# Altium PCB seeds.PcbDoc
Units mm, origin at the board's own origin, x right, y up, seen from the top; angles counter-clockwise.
Board outline 80 x 51 mm, 2 copper layers (Top Layer, Bottom Layer); 51 components, 49 nets, 224 pads, 44 vias.
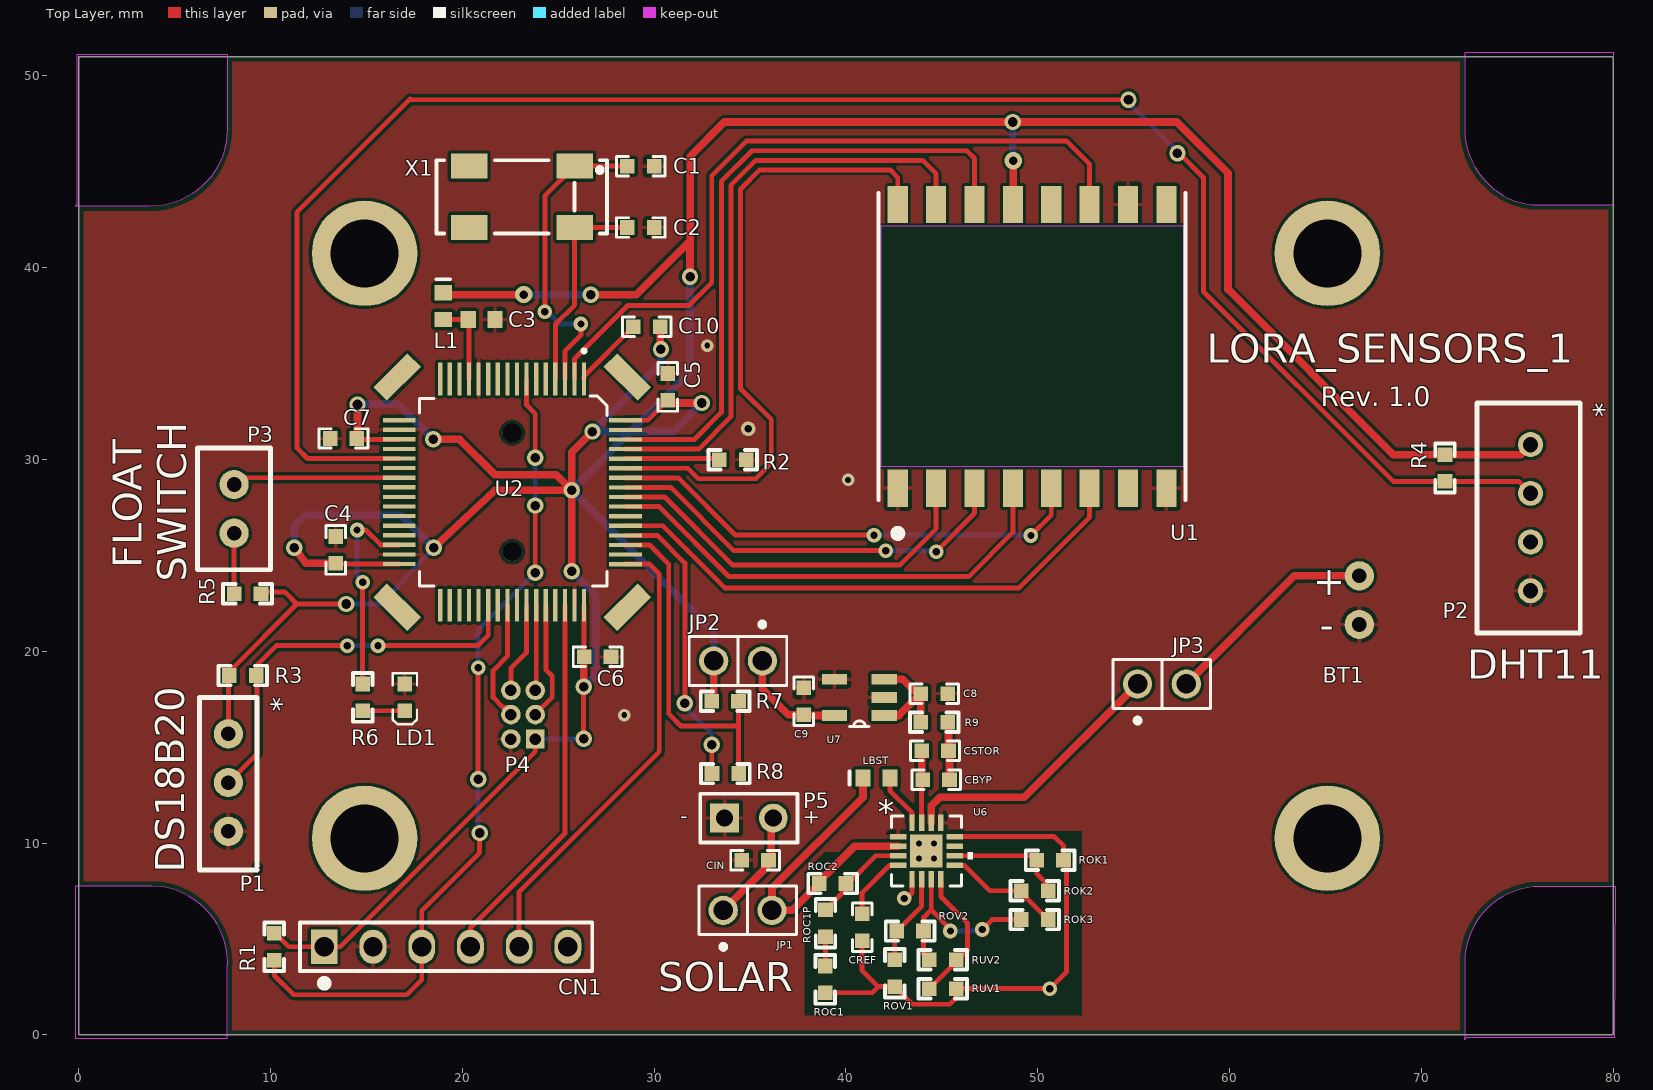
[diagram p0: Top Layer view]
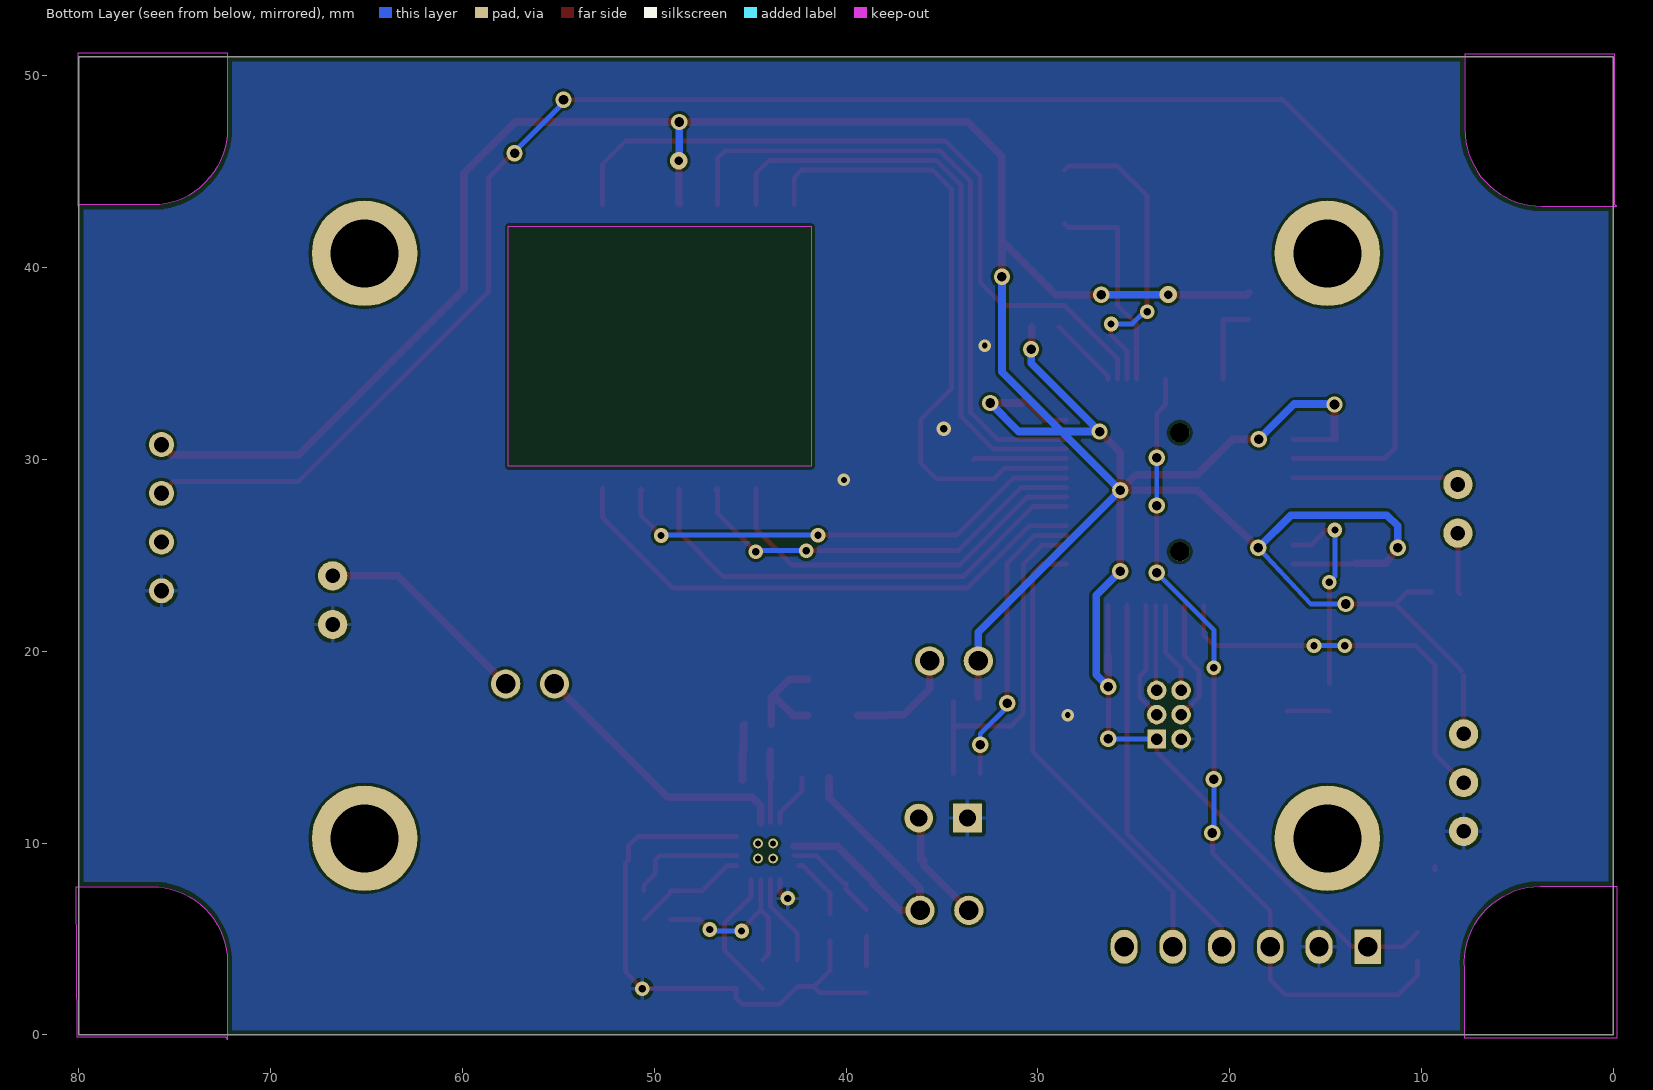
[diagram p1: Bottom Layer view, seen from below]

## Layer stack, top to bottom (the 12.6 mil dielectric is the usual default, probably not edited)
Top Solder: solder mask 0.0102, Solder Resist, Dk 3.5
Top Layer: signal copper 0.0356
Dielectric 1: dielectric 0.32, FR-4, Dk 4.8
Bottom Layer: signal copper 0.0356
Bottom Solder: solder mask 0.0102, Solder Resist, Dk 3.5

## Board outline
0,0 80,0 80,51 0,51
cut-out: 7.74,51.12 7.74,47.22 cw(c3.73,47.22) 3.73,43.21 -0.19,43.21 ccw(c-0.19,43.31) -0.09,43.31 -0.09,51.12
cut-out: 80.12,7.74 76.21,7.74 ccw(c76.21,3.78) 72.25,3.78 72.25,-0.24 cw(c72.38,-0.24) 72.38,-0.11 80.07,-0.11
cut-out: -0.18,-0.16 7.75,-0.16 7.75,3.46 ccw(c3.747,3.747) 3.46,7.75 -0.18,7.75
cut-out: 72.25,51.2 72.25,47.22 ccw(c76.162,47.22) 73.396,44.454 73.477,44.373 ccw(c76.115,47.011) 76.115,43.28 79.952,43.28 cw(c79.952,43.212) 80.02,43.212 80.02,51.2

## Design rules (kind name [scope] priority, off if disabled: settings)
BoardOutlineClearance [All] p1: gap=0.25 ignorepadtopadclearanceinfootprint=FALSE except(0: Arc-SplitContinuation Track-SplitContinuation SMDPad-SplitContinuation THPad-SplitContinuation Via-SplitContinuation Fill-SplitContinuation Poly-SplitContinuation Region-SplitContinuation Text-SplitContinuation)
Clearance Clearance-xPP-xTP-xTT [All] p1: gap=0.15 ignorepadtopadclearanceinfootprint=FALSE except(0: Arc-Hole Track-Hole SMDPad-Hole THPad-Hole Via-Hole Fill-Hole Poly-Hole Region-Hole Text-Hole)
ComponentClearance [All] p1: gap=0.25 collisioncheckmode=3 verticalgap=0.25 showdistances=FALSE
DiffPairsRouting [All] p1: maxlimit=0.25 minlimit=0.25 mostfreqgap=0.25 toplayer_minwidth=0.381 toplayer_maxwidth=0.381 toplayer_prefwidth=0.381 bottomlayer_minwidth=0.381 bottomlayer_maxwidth=0.381 bottomlayer_prefwidth=0.381 maxuncoupledlength=12.5
Height [All] p1: minheight=0 maxheight=25 prefheight=12.5
HoleSize HoleSize-PTH [All] p1: absolutevalues=TRUE maxlimit=3.6 minlimit=0.3 maxpercent=80.000 minpercent=20.000
HoleToHoleClearance [All] p1: gap=0.35 allowstackedmicrovias=TRUE
MinimumAnnularRing "Minimum IAR  >0.45mm" [((ObjectKind = 'Pad') OR (ObjectKind = 'Via')) And (Layer = 'MultiLayer') And (HoleDiameter > AsMM(0.45))] p1: minimumring=0.114 // minimum inner annular ring for pads > 0.45mm finished hole size
MinimumAnnularRing "Minimum IAR <=0.45mm" [((ObjectKind = 'Pad') OR (ObjectKind = 'Via')) And (Layer = 'MultiLayer') And (HoleDiameter <= AsMM(0.45))] p2: minimumring=0.175 // minimum inner annular ring for pads <= 0.45mm finished hole size
MinimumSolderMaskSliver [All] p1: minsoldermaskwidth=0.025
PlaneClearance PlaneClearance-IPI [All] p1: clearance=0.25
PlaneConnect [All] p1: planeconnectstyle=Relief reliefexpansion=0.175 reliefentries=4 reliefconductorwidth=0.2 reliefairgap=0.2
PolygonConnect PolygonConnect-xTW [All] p1: connectstyle=Relief reliefconductorwidth=0.2 reliefentries=4 polygonreliefangle="90 Angle" airgapwidth=0.2
RoutingCorners [All] p1: cornerstyle=45-Degree minsetback=2.5 maxsetback=2.5
RoutingVias "RoutingVias > 0.45mm" [(ObjectKind = 'Via') And (HoleDiameter > AsMM(0.45))] p1: holewidth=0.5 width=0.85 viastyle="Through Hole" minholewidth=0.5 minwidth=0.85 maxholewidth=0.9 maxwidth=1.25 // finishet hole size > 0.45mm
RoutingVias "RoutingVias <= 0.45mm" [(ObjectKind = 'Via') And (HoleDiameter <= AsMM(0.45))] p2: holewidth=0.3 width=0.65 viastyle="Through Hole" minholewidth=0.25 minwidth=0.6 maxholewidth=0.45 maxwidth=0.8 // finishet hole size <= 0.45mm
ShortCircuit ShortCircuit_1 [not InAnyNet vs not InAnyNet] p1: allowed=TRUE
ShortCircuit [All] p2: allowed=FALSE
SilkToSilkClearance [All] p1: silktosilkclearance=0
SilkToSolderMaskClearance SilkscreenOverComponentPads [IsPad] p1: minsilkscreentomaskgap=0.025 clearancetoexposedcopper=TRUE
SolderMaskExpansion [All] p1: expansion=0
UnRoutedNet [All] p1: checkbadconnections=TRUE
Width Width-xTW [All] p1: maxlimit=1.5 minlimit=0.15 preferedwidth=0.2
17 further rules are at their usual default settings.

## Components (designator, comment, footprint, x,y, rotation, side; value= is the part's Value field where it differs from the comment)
BT1 "battery" BATTERY 66.76,23.94 r270 top
C1 "10pF[N/A]" 0603C 29.3,45.3 r180 top value=10pF
C2 "10pF[N/A]" 0603C 29.3,42.1 r180 top value=10pF
C3 "Cap Semi" 1608[0603] 21,37.3 r0 top value=0.1µF
C4 "100nF" 0603C 13.39,25.29 r270 top value=0.1µF
C5 "100nF" 0603C 30.7,33.79 r270 top value=0.1µF
C6 "100nF" 0603C 27.05,19.71 r180 top value=0.1µF
C7 "100nF" 0603C 13.8,31.1 r0 top value=0.1uF
C8 "1uF" 0603C 44.6,17.8 r0 top value=1000pF
C9 "2.2uF" 0603C 37.8,17.4 r90 top value=2.2µF
C10 "100nF" 0603C 29.61,36.92 r0 top value=0.1µF
CBYP "C_BYP" 0603C 44.7,13.3 r180 top value=10pF
CIN "C_HVR" 0603C 35.26,9.11 r180 top value=4700pF
CN1 "Header 6X1" 1*6P 12.8,4.6 r0 top
CREF "C_REF" 0603C 40.844,5.619 r270 top value=10pF
CSTOR "C_STOR" 0603C 44.644,14.819 r180 top value=4.7µF
JP1 "JP2" SIP2/2.54 33.6,6.5 r0 top
JP2 "JP2" SIP2/2.54 35.64,19.5 r180 top
JP3 "JP2" SIP2/2.54 55.2,18.3 r0 top
L1 "Bead" INDC1608L 19,38 r270 top value="600 OHM"
LBST "Inductor" INDC1608L 41.59,13.4 r0 top value=22nH
LD1 "Green" 0603D 17,17.599 r270 top value=571nm
P1 "ds18b20" ds18b20 7.8,15.7 r270 top
P2 "dht11" dht11 75.69,30.78 r270 top
P3 "float_switch" float_switch 8.1,28.7 r270 top
P4 "header_3x2" header_3x2 22.53,15.43 r90 top
P5 "Header 2" HDR1X2 33.67,11.31 r0 top
R1 "4K7" 0603R 10.2,4.6 r270 top value="4.7 kOhms"
R2 "4K7" 0603R 34.1,30 r0 top value="4.7 kOhms"
R3 "4K7" 0603R 8.55,18.74 r0 top value="4.7 kOhms"
R4 "4K7" 0603R 71.23,29.56 r90 top value="4.7 kOhms"
R5 "4K7" 0603R 8.8,23 r0 top value="4.7 kOhms"
R6 "510" 0603R 14.8,17.6 r90 top value="510 Ohms"
R7 "1K" 0603R 33.7,17.4 r180 top value="1 kOhm"
R8 "1K" 0603R 33.71,13.63 r0 top value="1 kOhm"
R9 "" 0603R 44.6,16.3 r0 top value=0ohm
ROC1 "R_OC1" 0603R 38.92,2.9 r270 top value=5.76M
ROC1P "R_OC1Plus" 0603R 38.93,5.83 r270 top value=10M
ROC2 "R_OC2" 0603R 39.3,7.9 r0 top value=4.12M
ROK1 "R_OK1" 0603R 50.644,9.119 r180 top value=3.74Mohm
ROK2 "R_OK2" 0603R 49.844,7.519 r180 top value=5.23Mohm
ROK3 "R_OK3" 0603R 49.844,6.019 r180 top value="909 kOhms"
ROV1 "R_OV1" 0603R 42.544,3.219 r270 top value=4.53Mohm
ROV2 "R_OV2" 0603R 43.344,5.419 r180 top value=5.62Mohm
RUV1 "R_UV1" 0603R 45.044,2.419 r0 top value=4.99Mohm
RUV2 "R_UV2" 0603R 45.044,3.919 r0 top value=4.99Mohm
U1 "RFM95W-868S2" XCVR_RFM95W-868S2 49.7,35.9 r90 top
U2 "MCU_LQFP64" LQFP64 22.6,28.3 r180 top
U6 "BQ25504_RGT_16" RGT16_1P7X1P7 44.194,9.594 r0 top
U7 "TPS78330DDCR" SOT95P280X110-5N 40.7,17.6 r180 top
X1 "32.768K[N/A]" XTAL_4SM_8X3R8 23.1,43.7 r180 top

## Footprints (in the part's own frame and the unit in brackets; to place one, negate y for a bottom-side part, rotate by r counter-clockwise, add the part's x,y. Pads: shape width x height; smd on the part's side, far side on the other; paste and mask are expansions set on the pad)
1*6P [mil]
  rect 55x70 hole 40: 1(0,0)
  oval 55x70 hole 40: 2(400,0) 3(100,0) 4(300,0) 5(200,0) 6(500,0)
  silkscreen extent -50,-82 550,50
0603C [mil]
  rect 30x30 smd: 1(27.5,0) 2(-27.5,0)
  silkscreen extent -50,-20 50,20
0603D [mil]
  rect 30x30 smd: 1(27.5,0) 2(-27.5,0)
  silkscreen extent -50,-25 55,25
0603R [mil]
  rect 30x30 smd: 1(27.5,0) 2(-27.5,0)
  silkscreen extent -50,-20 50,20
1608[0603] [mm] "Chip Capacitor, Body 1.6x0.8mm, IPC High Density"
  rect 0.8x0.9 smd: 1(-0.7,0) 2(0.7,0)
  body extent -0.87,-0.48 0.87,0.48, height 1.3
BATTERY [mil]
  round 60 hole 30: +(0,0) -(100,0)
dht11 [mm]
  round 1.3 hole 0.8: 1(0,0) 2(2.54,0) 3(5.08,0) 4(7.62,0)
  silkscreen extent -2.17,-2.79 9.83,2.59
ds18b20 [mil]
  round 60 hole 30: 1(0,0) 2(100,0) 3(200,0)
  Top Layer lines w10: 279.53,59.06 271.65,59.06
  silkscreen extent -75,-59 280,59
float_switch [mil]
  round 60 hole 30: 1(100,0) 2(0,0)
  silkscreen extent -75,-75 175,75
HDR1X2 [mm] "Connector; Header; 2 Position"
  rect 1.5x1.5 hole 0.9: 1(0,0)
  round 1.5 hole 0.9: 2(2.54,0)
  silkscreen extent -1.27,-1.27 3.81,1.27
header_3x2 [mil]
  rect 38.62x38.62 hole 23.62: 1(0,-50)
  round 40 hole 23.58: 2(0,0) 3(50,-50) 4(50,0) 5(100,-50) 6(100,0)
INDC1608L [mm] "Chip Inductor, Body 1.6x0.8mm, IPC High Density"
  rect 0.8x0.9 smd: 1(-0.7,0) 2(0.7,0)
  silkscreen extent -1.4,-0.35 -1.4,0.35, body extent -0.87,-0.48 0.87,0.48, height 0.55
LQFP64 [mm]
  rect 1x2.5 smd rot 135: 0(-6,6) 0(6,-6)
  rect 1x2.5 smd rot 45: 0(-6,-6) 0(6,6)
  round 1 hole 1 unplated: 0(0,3.1) 0(0,-3.1)
  rect 0.22x1.7 smd: 1(-3.747,-5.901) 2(-3.247,-5.901) 3(-2.747,-5.901) 4(-2.247,-5.901) 5(-1.747,-5.901) 6(-1.247,-5.901) 7(-0.747,-5.901) 8(-0.247,-5.901) 9(0.253,-5.901) 10(0.753,-5.901) 11(1.253,-5.901) 12(1.753,-5.901) 13(2.253,-5.901) 14(2.753,-5.901) 15(3.253,-5.901) 16(3.753,-5.901) 33(3.753,5.902) 34(3.253,5.902) 35(2.753,5.902) 36(2.253,5.902) 37(1.753,5.902) 38(1.253,5.902) 39(0.753,5.902) 40(0.253,5.902) 41(-0.247,5.902) 42(-0.747,5.902) 43(-1.247,5.902) 44(-1.747,5.902) 45(-2.247,5.902) 46(-2.747,5.902) 47(-3.247,5.902) 48(-3.747,5.901)
  rect 1.7x0.22 smd: 17(5.901,-3.753) 18(5.901,-3.253) 19(5.901,-2.753) 20(5.901,-2.253) 21(5.901,-1.753) 22(5.901,-1.253) 23(5.901,-0.753) 24(5.901,-0.253) 25(5.901,0.247) 26(5.901,0.747) 27(5.901,1.247) 28(5.901,1.747) 29(5.901,2.247) 30(5.901,2.747) 31(5.901,3.247) 32(5.901,3.747) 49(-5.902,3.753) 50(-5.902,3.253) 51(-5.902,2.753) 52(-5.902,2.253) 53(-5.902,1.753) 54(-5.902,1.253) 55(-5.902,0.753) 56(-5.902,0.253) 57(-5.902,-0.247) 58(-5.902,-0.747) 59(-5.902,-1.247) 60(-5.902,-1.747) 61(-5.902,-2.247) 62(-5.902,-2.746) 63(-5.902,-3.246) 64(-5.902,-3.746)
  silkscreen extent -4.94,-7.42 4.84,4.89
RGT16_1P7X1P7 [mm]
  rect 0.85x0.28 smd paste-0.14: 1(-1.475,0.75) 2(-1.475,0.25) 3(-1.475,-0.25) 4(-1.475,-0.75) 9(1.475,-0.75) 10(1.475,-0.25) 11(1.475,0.25) 12(1.475,0.75)
  rect 0.28x0.85 smd paste-0.14: 5(-0.75,-1.475) 6(-0.25,-1.475) 7(0.25,-1.475) 8(0.75,-1.475) 13(0.75,1.475) 14(0.25,1.475) 15(-0.25,1.475) 16(-0.75,1.475)
  rect 1.7x1.7 smd paste-0.837 mask-0.838: 17(0,0)
  round 0.508 / inner round 1.524 / far side round 0.508 hole 0.3: V(-0.394,-0.394) V(-0.394,0.394) V(0.394,-0.394) V(0.394,0.394)
  silkscreen extent -1.83,-1.83 2.41,1.83, body extent -1.63,-1.63 1.63,1.63, height 1
SIP2/2.54 [mil]
  round 60 hole 40: 1(0,0) 2(100,0)
  silkscreen extent -50,-80 150,50
SOT95P280X110-5N [mil]
  rect 52x22 smd: 1(-51,37) 2(-51,0) 3(-51,-37) 4(51,-37) 5(51,37)
  silkscreen extent -20,48 20,60
XCVR_RFM95W-868S2 [mm]
  rect 1.95x1.05 smd: 1(-7.4,7) 2(-7.4,5) 3(-7.4,3) 4(-7.4,1) 5(-7.4,-1) 6(-7.4,-3) 7(-7.4,-5) 8(-7.4,-7) 9(7.4,-7) 10(7.4,-5) 11(7.4,-3) 12(7.4,-1) 13(7.4,1) 14(7.4,3) 15(7.4,5) 16(7.4,7)
  silkscreen extent -10.04,-8 8,8
XTAL_4SM_8X3R8 [mm]
  rect 1.9x1.3 smd: 1(-2.75,-1.6) 2(2.75,-1.6) 3(2.75,1.6) 4(-2.75,1.6)
  silkscreen extent -4.45,-1.91 4.44,1.91

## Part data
BT1 JP1 JP2 JP3 P3: Manufacturer="Harwin Inc."
C1 C9 CBYP CREF: library part Cap, "Capacitor", Manufacturer="Murata Electronics North America"
C2: library part CAP, "Capacitor", Manufacturer="Murata Electronics North America"
C3: "Capacitor (Semiconductor SIM Model)", Manufacturer="AVX Corporation"
C4 C5 C6 C7 C8 C10: library part Cap, "Capacitor", Manufacturer="AVX Corporation"
CIN: library part Cap, "Capacitor", Manufacturer=TDK
CN1: "Header, 6-Pin, Single row", Manufacturer=Molex
CSTOR: library part Cap, "Capacitor", Manufacturer="Taiyo Yuden"
L1: library part Inductor, "Inductor", Manufacturer="Taiyo Yuden"
LBST: Manufacturer="Johanson Technology"
LD1: library part LED2, "Typical RED, GREEN, YELLOW, AMBER GaAs LED", Manufacturer=Lite-On
P1: Manufacturer="Wurth Electronics"
P4: Manufacturer="Amphenol FCI"
P5: "Header, 2-Pin", Manufacturer="Harwin Inc."
R1 R2 R3 R4 R5 R9 ROC1P ROK3: library part Res1, "Resistor", Manufacturer=Yageo
R6: library part Res1, "Resistor", Manufacturer="Rohm Semiconductor"
R7 R8: library part Res1, "Resistor", Manufacturer=Susumu
ROC1 ROC2 ROK2 RUV1 RUV2: library part Res1, "Resistor", Manufacturer="Vishay Dale"
ROK1 ROV1 ROV2: library part Res1, "Resistor", Manufacturer="Stackpole Electronics Inc."
U1: Manufacturer="RF Solutions", Package="SMD-16 Hope Microelectronics"
U2: Manufacturer=STM
U6: "Imported", Manufacturer="Texas Instruments", PACKAGE_DESIGNATOR=RGT
U7: "IC REG LINEAR 3V 150MA SOT23-5", Manufacturer="Texas Instruments", Package="SOT-23-5 Texas Instruments"
X1: library part MC306

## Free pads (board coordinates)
  round 5.5 hole 3.55: 11(14.9,10.25) 12(14.9,40.75) 13(65.1,10.25) 14(65.1,40.75)
  round 0.85 hole 0.5: 27(25.7,28.4)

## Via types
v1: diameter 0.85, hole 0.5, Top Layer to Bottom Layer, 23 vias
v2: diameter 0.762, hole 0.381, Top Layer to Bottom Layer, 16 vias
v3: diameter 0.65, hole 0.3, Top Layer to Bottom Layer, 3 vias
v4: diameter 0.9, hole 0.45, Top Layer to Bottom Layer, 2 vias

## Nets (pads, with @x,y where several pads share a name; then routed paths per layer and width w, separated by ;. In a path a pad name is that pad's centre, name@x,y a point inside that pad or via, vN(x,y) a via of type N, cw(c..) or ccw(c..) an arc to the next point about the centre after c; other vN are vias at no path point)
GND: BT1.- C1.2 C2.2 C3.2 C4.2 C5.2 C6.2 C7.2 C8.1 C9.1 CIN.1 CN1.3 CREF.1 LD1.2 P1.3 P2.4 P4.2 P5.1 R2.1 ROC1.1 ROK1.2 ROV1.1 RUV1.1 U1.1 U1.8 U1.10 U2.12 U2.18 U2.31 U2.47 U2.63 U6.1 U6.5 U6.12 U6.13 U7.2 U7.4 | length 30.6
  Top Layer w0.254: ROC1.1 41.361,2.201 41.68,2.52 ; CREF.1 40.844,3.356 41.68,2.52 ; v2(43.04,7.12) 43.15,7.12 43.444,7.414 U6.5 ; U6.12 50.856,10.344 51.342,9.858 ROK1.2 51.5,8.961 51.5,3.3 v2(50.619,2.419) RUV1.1 45.742,1.942 45.4,1.6 43.464,1.6 ROV1.1 41.68,2.52
  other v2: 34.9,31.6
  other v3: 28.44,16.68 40.11,28.94 32.77,35.94
NetBT1_+: BT1.+ JP3.2 | length 11.4
  Top Layer w0.4: JP3.2 63.38,23.94 BT1.+
NetC1_1: C1.1 U2.3 X1.1 | length 16.4
  Top Layer w0.254: v2(24.3,37.7) 24.3,43.75 X1.1 28.403,45.3 C1.1@28.603,45.1 ; U2.3 25.347,35.647 26.18,36.48 v2(26.18,37.07)
  Bottom Layer w0.254: v2(24.3,37.7) 24.44,37.7 25.07,37.07 v2(26.18,37.07)
NetC2_1: C2.1 U2.4 X1.4 | length 11.2
  Top Layer w0.254: U2.4 24.847,37.047 25.85,38.05 X1.4 28.403,42.1 C2.1@28.603,42.3
NetC3_1: C3.1 L1.2 U2.13 | length 4.4
  Top Layer w0.254: L1.2 C3.1 ; U2.13 C3.1@20.347,37.3
NetC8_2: C8.2 R9.2 U7.1 U7.3 | length 5.9
  Top Layer w0.4: U7.1 42.76,16.66 43.7,17.6 43.901,17.399 R9.2 R9.2@43.901,16.2 ; U7.3 42.962,18.54 C8.2@43.901,17.6
NetC9_2: C9.2 JP2.1 U7.5 | length 5.8
  Top Layer w0.254: C9.2 C9.2@37.841,16.66
  Top Layer w0.4: JP2.1 35.64,18.06 36.998,16.702 C9.2 ; C9.2@37.841,16.66 U7.5
NetC10_2: C10.2 U2.1 | length 3.8
  Top Layer w0.254: U2.1 26.347,34.355 C10.2
NetCBYP_1: CBYP.1 CSTOR.1 U6.15 | length 3.8
  Top Layer w0.254: U6.15 CBYP.1@43.944,13.417
  Top Layer w0.4: CBYP.1@43.944,13.417 43.945,13.419 CSTOR.1
NetCBYP_2: CBYP.2 CSTOR.2 R9.1 | length 2.9
  Top Layer w0.4: R9.1@45.298,16.2 45.342,16.156 CSTOR.2 45.398,14.762 CBYP.2
NetCIN_2: CIN.2 JP1.1 P5.2 | length 5.8
  Top Layer w0.4: JP1.1 35.959,8.859 CIN.2 ; CIN.2@36.099,9.11 P5.2@36.099,11.31
NetCREF_2: CREF.2 U6.4 | length 3.3
  Top Layer w0.254: CREF.2 40.844,7.417 42.264,8.837 U6.4@42.488,8.837
NetJP1_2: JP1.2 LBST.1 ROC2.2 U6.2 | length 16.9
  Top Layer w0.4: LBST.1 40.89,12.39 36.14,7.64 JP1.2 37.202,6.5 ROC2.2 38.602,8.002 40.444,9.844 U6.2
NetJP3_1: JP3.1 U6.14 | length 14.3
  Top Layer w0.4: U6.14 44.444,11.944 44.9,12.4 49.3,12.4 JP3.1
NetLBST_2: LBST.2 U6.16 | length 2.8
  Top Layer w0.254: LBST.2 42.29,12.74 43.444,11.586 U6.16
NetLD1_1: LD1.1 R6.2 | length 2.2
  Top Layer w0.254: R6.2 LD1.1 LD1.1
NetP3_1: P3.1 R5.2 | length 3.2
  Top Layer w0.254: R5.2@8,23 8.1,23.1 P3.1
NetR2_2: R2.2 U2.60 | length 4.9
  Top Layer w0.254: U2.60 33.303,30.047 R2.2@33.35,30
NetROC1_2: ROC1.2 ROC1P.1 | length 1.5
  Top Layer w0.254: ROC1.2 38.93,3.608 ROC1P.1
NetROC1P_2: ROC1P.2 ROC2.1 U6.3 | length 5.1
  Top Layer w0.254: ROC1P.2 39.999,7.597 ROC2.1 40.11,7.9 41.554,9.344 U6.3
NetROK1_1: ROK1.1 ROK2.2 U6.10 | length 6.2
  Top Layer w0.254: U6.10 49.72,9.344 ROK1.1 49.945,8.4 50.542,7.803 ROK2.2
NetROK2_1: ROK2.1 ROK3.2 U6.9 | length 6.1
  Top Layer w0.254: U6.9 46.171,8.844 47.496,7.519 ROK2.1 49.145,7.416 ROK3.2
NetROK3_1: ROK3.1 ROV2.2 RUV2.2 U6.7 | length 10
  Top Layer w0.254: RUV2.2 44.042,4.222 ROV2.2 44.042,6.117 44.444,6.519 ; U6.7 44.444,6.519 ; v2(45.444,5.419) 45.444,5.519 44.444,6.519 ; v2(47.1,5.5) 47.619,6.019 ROK3.1
  Bottom Layer w0.254: v2(45.444,5.419) 47.019,5.419 v2(47.1,5.5)
NetROV1_2: ROV1.2 ROV2.1 U6.6 | length 4.8
  Top Layer w0.254: ROV1.2 42.544,5.317 ROV2.1 43.944,6.717 43.944,7.617 U6.6
NetRUV1_2: RUV1.2 RUV2.1 U6.8 | length 7.1
  Top Layer w0.254: RUV1.2 46.344,4.417 46.344,5.819 44.944,7.218 U6.8
NRST: CN1.5 R1.1 U2.7 | length 43.7
  Top Layer w0.254: R1.1@10.2,3.85 10.2,3.1 11.2,2.1 17.1,2.1 17.88,2.88 CN1.5 17.88,6.48 20.9,9.5 v1(20.9,10.53) ; v1(20.82,13.33) v2(20.82,19.15) ; U2.7 23.347,32.843 23.8,32.39 v1(23.8,30.1) ; v1(23.8,24.1) v1(23.8,27.6) v1@23.8,27.8
  Bottom Layer w0.254: v1@20.82,10.53 v1(20.82,13.33) ; v2(20.82,19.15) 20.82,21.12 v1(23.8,24.1) ; v1(20.9,10.53) v1@20.9,10.9 ; v1(23.8,27.6) v1(23.8,30.1)
PA5: P2.2 R4.2 U2.21 | length 96.8
  Top Layer w0.254: U2.21 11.927,30.053 11.37,30.61 11.37,42.89 17.29,48.81 17.34,48.76 v1(54.73,48.76) ; v1(57.28,45.97) 57.37,45.97 58.64,44.7 58.64,38.751 68.53,28.862 R4.2 75.069,28.862 P2.2
  Bottom Layer w0.254: v1(54.73,48.76) 54.73,48.61 57.28,46.06 v1(57.28,45.97)
PA7: P3.2 U2.23 | length 8.7
  Top Layer w0.254: P3.2 8.453,29.053 U2.23
PA9: P4.6 U2.42 | length 4.8
  Top Layer w0.254: P4.6 22.53,19.13 23.347,19.947 U2.42
PA10: P4.5 U2.43 | length 4.4
  Top Layer w0.254: P4.5 23.851,18.021 U2.43@23.851,22.399
PA11: P4.3 U2.44 | length 6.4
  Top Layer w0.254: P4.3 23.8,17.085 24.167,17.085 24.685,17.603 24.685,18.715 24.355,19.045 U2.44@24.355,22.399
PB3: U1.4 U2.55 | length 25
  Top Layer w0.254: U2.55 30.253,27.547 33.9,23.9 46.4,23.9 48.7,26.2 U1.4
PB4: U1.2 U2.56 | length 20.6
  Top Layer w0.254: U2.56 30.553,28.047 34.1,24.5 42.8,24.5 44.7,26.4 U1.2
PB5: U1.3 U2.57 | length 21.9
  Top Layer w0.254: U2.57 30.853,28.547 34.15,25.25 v2(42.07,25.25) ; v2(44.7,25.2) 46.7,27.2 U1.3 U1.3@46.8,28.4
  Bottom Layer w0.254: v2(42.07,25.25) 44.65,25.25 v2(44.7,25.2)
PB6: U1.5 U2.58 | length 25.4
  Top Layer w0.254: U2.58 31.253,29.047 34.24,26.06 v2(41.46,26.06) ; v2(49.64,26.04) 50.7,27.1 U1.5 U1.5@50.6,28.4
  Bottom Layer w0.254: v2(41.46,26.06) 49.62,26.06 v2(49.64,26.04)
PB7: U1.16 U2.59 | length 33.3
  Top Layer w0.254: U2.59 31.753,29.547 32.3,29 35.3,29 36.1,29.8 36.1,32.1 34.5,33.7 34.5,44.1 35.5,45.1 42.3,45.1 42.7,44.7 U1.16
PB8: U1.15 U2.61 | length 31.4
  Top Layer w0.254: U2.61 32.317,30.547 34,32.23 34,44.3 35.3,45.6 44,45.6 44.7,44.9 U1.15
PB9: U1.14 U2.62 | length 34.1
  Top Layer w0.254: U2.62 32.087,31.047 33.5,32.46 33.5,44.5 35.1,46.1 46.3,46.1 46.7,45.7 U1.14
PB11: R6.1 U2.30 | length 10.7
  Top Layer w0.254: v2(14.51,26.33) 14.96,26.33 15.736,25.554 U2.30 ; R6.1 v2(14.8,23.6)
  Bottom Layer w0.254: v2(14.51,26.33) 14.51,23.89 v2(14.8,23.6)
PC7: P1.2 R3.1 U2.38 | length 21
  Top Layer w0.254: P1.2 9.297,14.657 9.297,19.297 10.3,20.3 v2(14,20.3) ; v2(15.6,20.3) 20.8,20.3 21.347,20.847 U2.38
  Bottom Layer w0.254: v2(14,20.3) v2(15.6,20.3)
PC9: P4.4 U2.40 | length 6.6
  Top Layer w0.254: U2.40 22.347,19.747 21.6,19 21.6,17.6 22.115,17.085 22.53,17.085 P4.4
PC10: R7.2 R8.1 U2.51 | length 18.2
  Top Layer w0.254: U2.51 29.763,25.547 30.76,24.55 30.76,16.74 31.4,16.1 34.397,16.1 34.399,16.101 ; R8.1@34.399,13.63 34.399,16.101 ; R7.2 34.399,16.101
PC11: R8.2 U2.52 | length 15.3
  Top Layer w0.254: U2.52 30.153,26.047 31.6,24.6 v1(31.6,17.3) ; v1(33.002,15.13) 33.002,13.64 R8.2
  Bottom Layer w0.254: v1(31.6,17.3) 31.6,17.1 33.002,15.698 v1(33.002,15.13)
PC12: U1.6 U2.53 | length 28.6
  Top Layer w0.254: U2.53 30.453,26.547 33.7,23.3 49,23.3 52.7,27 U1.6
PC13: U1.11 U2.2 | length 38.5
  Top Layer w0.254: U2.2 25.847,35.247 28.63,38.03 31.81,38.03 33,39.22 33,44.8 34.8,46.6 51.5,46.6 52.7,45.4 U1.11
SWO: CN1.6
TCK: CN1.2 U2.49 | length 24.4
  Top Layer w0.254: CN1.2 22.96,7.46 30.266,14.766 30.266,24.034 29.753,24.547 U2.49
TMS: CN1.4 U2.46 | length 19.8
  Top Layer w0.254: CN1.4 20.42,5.577 25.347,10.503 U2.46
VDD: C4.1 C5.1 C6.1 C7.1 C10.1 CN1.1 JP2.2 L1.1 P1.1 P2.1 P4.1 pad.27 R1.2 R3.2 R4.1 R5.1 R7.1 U1.13 U2.19 U2.32 U2.48 U2.64 | length 227.5
  Top Layer w0.254: P1.1 R3.2@7.8,18.74 ; R3.2@7.947,18.953 7.9,19 11.37,22.47 ; R5.1@9.499,23.1 10.74,23.1 11.37,22.47 ; R1.2@10.2,5.35 10.95,4.6 CN1.1 13.63,4.6 23.8,14.77 P4.1 ; C4.1@13.39,24.554 U2.32 ; v1(13.94,22.47) 11.37,22.47 ; C7.1 14.545,31.053 U2.19 ; v1(26.32,15.44) v1(26.32,18.15) ; C6.1@26.347,19.715 U2.48 ; U2.64 29.655,32.047 C5.1 ; U1.13@48.66,43.34 U1.13
  Top Layer w0.4: v1(11.24,25.4) 11.849,24.592 C4.1 ; C7.1 14.53,31.131 v1(14.53,32.87) ; v1(18.477,31.053) 19.847,31.053 21.7,29.2 24.9,29.2 pad.27 ; v1(18.5,25.4) 21.7,28.4 pad.27 ; L1.1 19.1,38.6 v4(23.2,38.6) ; v1(25.7,24.17) pad.27 ; v1(26.32,18.15) C6.1@26.32,19.679 ; C6.1@26.347,19.715 C6.1 ; v1(26.7,38.6) 29.06,38.6 31.85,41.39 ; v1(26.78,31.46) 25.7,30.38 pad.27 ; C10.1 30.308,35.792 v1(30.35,35.75) ; C5.1 30.842,32.95 v1(32.48,32.95) ; v1(31.87,39.53) 31.87,41.37 31.85,41.39 ; R7.1@33.1,17.6 JP2.2 ; U1.13@48.66,43.34 48.72,43.4 v4(48.72,45.58) ; P2.1 75.169,30.259 R4.1 68.53,30.259 59.92,38.868 59.92,44.93 57.25,47.6 v1(48.69,47.6) 33.66,47.6 31.88,45.82 31.88,41.42 31.85,41.39
  Bottom Layer w0.254: v1(13.94,22.47) 15.77,22.47 v1(18.5,25.4) ; P4.1 23.81,15.44 v1(26.32,15.44)
  Bottom Layer w0.4: v1(11.24,25.4) 11.24,26.54 11.8,27.1 16.8,27.1 v1(18.5,25.4) ; v1(14.53,32.87) 14.56,32.9 16.63,32.9 v1(18.477,31.053) ; v4(23.2,38.6) v1(26.7,38.6) ; v1(25.7,24.17) 26.95,22.92 26.95,18.78 v1(26.32,18.15) ; v1(30.35,35.75) 30.35,35.03 v1(26.78,31.46) 28.76,31.46 ; v1(31.87,39.53) 31.87,34.57 28.76,31.46 ; v1(32.48,32.95) 30.99,31.46 28.76,31.46 ; JP2.2 33.1,21 pad.27 28.76,31.46 ; v1(48.69,47.6) 48.69,45.61 v4(48.72,45.58)
pads on no net: P2.3 U1.7 U1.9 U1.12 U2.0 U2.5 U2.6 U2.8 U2.9 U2.10 U2.11 U2.14 U2.15 U2.16 U2.17 U2.20 U2.22 U2.24 U2.25 U2.26 U2.27 U2.28 U2.29 U2.33 U2.34 U2.35 U2.36 U2.37 U2.39 U2.41 U2.45 U2.50 U2.54 U6.11 U6.17 U6.V X1.2 X1.3

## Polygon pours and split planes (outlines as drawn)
GND on Top Layer "Top Layer-No Net" (solid, pour order 10): -0.09,51.12 -0.09,-0.07 -0.13,-0.11 80.07,-0.11 80.07,51.15 80.02,51.2
GND on Bottom Layer "Top Layer-No Net" (solid, pour order 12): -0.09,51.12 -0.18,51.03 -0.18,-0.16 80.02,-0.16 80.07,-0.11 80.02,-0.06 80.02,51.2

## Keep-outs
Keep-Out Layer:
  rectangle: 41.8,29.64 57.6,42.16

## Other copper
Top Layer:
  pour cut-out: 42.238,9.54 38.9,9.54 37.83,8.47 37.84,8.46 37.84,1.02 52.3,1.02 52.31,1.03 52.29,1.05 52.29,10.62 46.53,10.62 46.5,10.65 46.42,10.57 43.868,10.57

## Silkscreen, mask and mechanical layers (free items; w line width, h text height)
Top Overlay:
  text "LORA_SENSORS_1" at 58.82,35.04 h1.52
  text "Rev. 1.0" at 64.76,32.79 h1.02
  text "FLOAT" at 3.28,24.34 h1.52 r90
  text "SWITCH" at 5.6,23.62 h1.52 r90
  text "DHT11" at 72.4,18.56 h1.52
  text "-" at 31.35,11.04 h0.8
  text "+" at 37.74,11.02 h0.8
  text "DS18B20" at 5.49,8.46 h1.52 r90
  text "SOLAR" at 30.21,2.29 h1.52
Mechanical 1:
  lines w0.013: 203.774,40.702 204.774,40.702 ; 211.73,38.884 212.73,38.884 ; 203.774,40.552 203.774,40.852 ; 203.774,40.552 204.774,40.702 ; 203.774,40.552 203.774,40.852 ; 203.774,40.552 204.774,40.702 ; 203.774,40.852 204.774,40.702 ; 203.774,40.852 204.774,40.702 ; 211.73,38.734 211.73,39.034 ; 211.73,38.734 212.73,38.884 ; 211.73,38.734 211.73,39.034 ; 211.73,38.734 212.73,38.884 ; 211.73,39.034 212.73,38.884 ; 211.73,39.034 212.73,38.884
Mechanical 9:
  circle w0.013: c65.1,10.25 r1.75
  circle w0.013: c65.1,40.75 r1.75
  circle w0.013: c14.9,40.75 r1.75
  circle w0.013: c14.9,10.25 r1.75
  lines w0.013: 76.25,7.75 ccw(c76.25,3.75) 72.25,3.75 72.25,0 7.75,0 7.75,3.75 ccw(c3.75,3.75) 3.75,7.75 0,7.75 0,43.25 3.75,43.25 ccw(c3.75,47.25) 7.75,47.25 7.75,51 72.25,51 72.25,47.25 ccw(c76.25,47.25) 76.25,43.25 80,43.25 80,7.75 76.25,7.75 ; 76.25,7.75 76.25,7.75
Mechanical 11:
  circle w0.006: c203.602,44 r0.003
  circle w0.006: c204.774,40.702 r0.003
  circle w0.006: c215.338,35.851 r0.003
  circle w0.006: c212.73,38.884 r0.003
  circle w0.006: c204.188,42.351 r0.003
  circle w0.006: c204.188,72.851 r0.003
  circle w0.006: c204.188,42.351 r0.003
  circle w0.006: c153.988,42.351 r0.003
  circle w0.006: c146.838,32.101 r0.003
  circle w0.006: c146.838,83.101 r0.003
  circle w0.006: c139.088,75.351 r0.003
  circle w0.006: c139.088,39.851 r0.003
  circle w0.006: c211.338,83.101 r0.003
  circle w0.006: c146.838,83.101 r0.003
  circle w0.006: c219.088,75.351 r0.003
  circle w0.006: c139.088,75.351 r0.003
  circle w0.006: c-4.531,50.931 r0.003
  circle w0.006: c4.769,46.631 r0.003
  circle w0.006: c-17.231,50.28 r0.003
